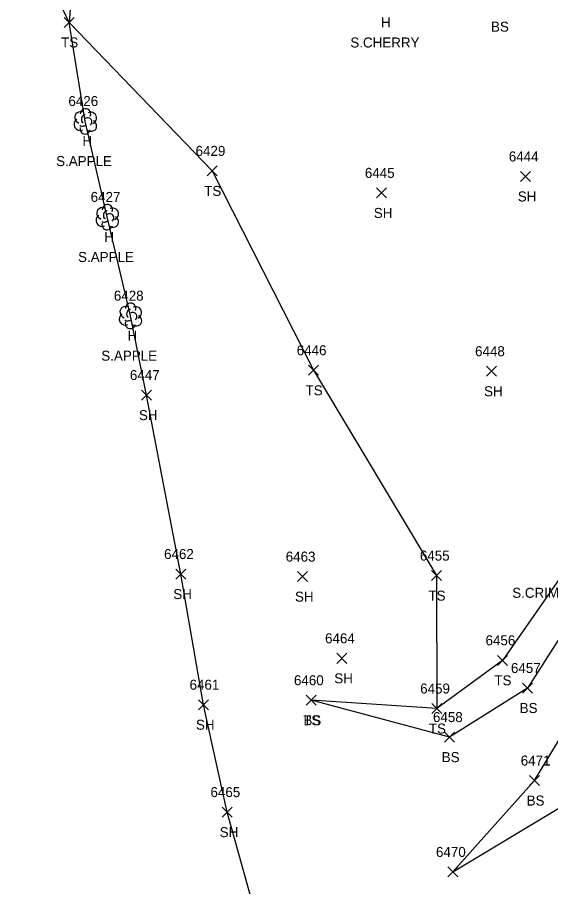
# Model space of a CAD drawing. Extents: x 1472233 to 1475777, y 540726 to 543442.
# Drawn here: x 1472240.2 to 1472346.8, y 541495 to 541668.7 of the extents above; entities that cross this region are included whole.
import ezdxf

# ---------------------------------------------------------------- set-up
doc = ezdxf.new("R2010")
doc.units = 0
for name, color, linetype in [('L_A', 7, 'Continuous'), ('L_C', 7, 'Continuous'), ('L_I', 7, 'Continuous'), ('L_TIC', 7, 'Continuous'), ('LELB', 7, 'Continuous'), ('LSOGP', 7, 'Continuous'), ('LTD', 7, 'Continuous')]:
    doc.layers.add(name, color=color, linetype=linetype)

msp = doc.modelspace()

# ---------------------------------------------------------------- linework, layer by layer
at = {"layer": 'L_TIC'}
for points in [[(1472249.53, 541666.66), (1472251.53, 541668.66)], [(1472251.53, 541666.66), (1472249.53, 541668.66)], [(1472278.15, 541636.99), (1472280.15, 541638.99)], [(1472280.15, 541636.99), (1472278.15, 541638.99)], [(1472340.77, 541635.88), (1472342.77, 541637.88)], [(1472342.77, 541635.88), (1472340.77, 541637.88)], [(1472311.99, 541632.59), (1472313.99, 541634.59)], [(1472313.99, 541632.59), (1472311.99, 541634.59)], [(1472298.42, 541597.15), (1472300.42, 541599.15)], [(1472300.42, 541597.15), (1472298.42, 541599.15)], [(1472334.03, 541596.96), (1472336.03, 541598.96)], [(1472336.03, 541596.96), (1472334.03, 541598.96)], [(1472265.01, 541592.19), (1472267.01, 541594.19)], [(1472267.01, 541592.19), (1472265.01, 541594.19)], [(1472271.89, 541556.43), (1472273.89, 541558.43)], [(1472273.89, 541556.43), (1472271.89, 541558.43)], [(1472296.21, 541555.92), (1472298.21, 541557.92)], [(1472298.21, 541555.92), (1472296.21, 541557.92)], [(1472322.99, 541556.12), (1472324.99, 541558.12)], [(1472324.99, 541556.12), (1472322.99, 541558.12)], [(1472304.08, 541539.59), (1472306.08, 541541.59)], [(1472306.08, 541539.59), (1472304.08, 541541.59)], [(1472336.17, 541539.19), (1472338.17, 541541.19)], [(1472338.17, 541539.19), (1472336.17, 541541.19)], [(1472341.19, 541533.66), (1472343.19, 541535.66)], [(1472343.19, 541533.66), (1472341.19, 541535.66)], [(1472276.42, 541530.32), (1472278.42, 541532.32)], [(1472278.42, 541530.32), (1472276.42, 541532.32)], [(1472297.94, 541531.21), (1472299.94, 541533.21)], [(1472299.94, 541531.21), (1472297.94, 541533.21)], [(1472297.94, 541531.21), (1472299.94, 541533.21)], [(1472299.94, 541531.21), (1472297.94, 541533.21)], [(1472323.06, 541529.56), (1472325.06, 541531.56)], [(1472325.06, 541529.56), (1472323.06, 541531.56)], [(1472323.06, 541529.56), (1472325.06, 541531.56)], [(1472325.06, 541529.56), (1472323.06, 541531.56)], [(1472325.61, 541523.85), (1472327.61, 541525.85)], [(1472327.61, 541523.85), (1472325.61, 541525.85)], [(1472342.59, 541515.17), (1472344.59, 541517.17)], [(1472344.59, 541515.17), (1472342.59, 541517.17)], [(1472281.16, 541508.86), (1472283.16, 541510.86)], [(1472283.16, 541508.86), (1472281.16, 541510.86)], [(1472326.29, 541496.9), (1472328.29, 541498.9)], [(1472328.29, 541496.9), (1472326.29, 541498.9)], [(1472326.29, 541496.9), (1472328.29, 541498.9)], [(1472328.29, 541496.9), (1472326.29, 541498.9)]]:
    msp.add_lwpolyline(points, dxfattribs=at)
at = {"layer": 'LELB'}
for points in [[(1472309.17, 541764.66), (1472314.54, 541746.81), (1472319.35, 541731.08), (1472317.7, 541714.57), (1472324.89, 541681.45), (1472336.46, 541670.81), (1472359.1, 541676.99), (1472364.9, 541640.23), (1472367.87, 541606.27), (1472368.21, 541581.12), (1472358.44, 541560.08), (1472342.19, 541534.66), (1472326.61, 541524.85), (1472298.94, 541532.21)], [(1472299.33, 541724.33), (1472289.98, 541730.07), (1472268.13, 541729.15), (1472253.22, 541721.94), (1472256.99, 541708.73), (1472252.51, 541693.36), (1472250.53, 541667.66), (1472279.15, 541637.99), (1472299.42, 541598.15), (1472323.99, 541557.12), (1472324.06, 541530.56)], [(1472367.87, 541606.27), (1472352.19, 541561.68), (1472337.17, 541540.19), (1472324.06, 541530.56), (1472298.94, 541532.21)], [(1472327.29, 541497.9), (1472343.59, 541516.17), (1472358.91, 541541.46), (1472365.97, 541555.39), (1472373.3, 541567.63), (1472375.91, 541562.06), (1472383.59, 541551.03), (1472407.94, 541534.18), (1472426.61, 541529.13), (1472462.11, 541538.21), (1472496.31, 541549.57), (1472514.24, 541561.59), (1472528.33, 541570.22)], [(1472327.29, 541497.9), (1472350.15, 541511.62), (1472363.37, 541538.44), (1472369.55, 541552.47), (1472375.91, 541562.06)]]:
    msp.add_lwpolyline(points, dxfattribs=at)
at = {"layer": 'LSOGP'}
msp.add_lwpolyline([(1472289.68, 541482.89), (1472282.16, 541509.86), (1472277.42, 541531.32), (1472272.89, 541557.43), (1472266.01, 541593.19), (1472262.79, 541609.06), (1472258.15, 541628.79), (1472253.76, 541647.95), (1472250.53, 541667.66), (1472240.2, 541689.37)], dxfattribs=at)
at = {"layer": 'LTD'}
for p, q in [((1472253.76, 541647.95), (1472253.76, 541647.95)), ((1472253.76, 541647.95), (1472253.76, 541647.95)), ((1472258.15, 541628.79), (1472258.15, 541628.79)), ((1472258.15, 541628.79), (1472258.15, 541628.79)), ((1472262.79, 541609.06), (1472262.79, 541609.06)), ((1472262.79, 541609.06), (1472262.79, 541609.06))]:
    msp.add_line(p, q, dxfattribs=at)
for centre in [(1472253.81, 541649.38), (1472258.2, 541630.22), (1472262.84, 541610.5)]:
    msp.add_arc(centre, 1.05, 335.5272, 180.9563, dxfattribs=at)
for centre, major_axis, ratio, start_param, end_param in [((1472252.97, 541648.62), (1.21, -0.51), 0.895232, 1.570796, 4.712389), ((1472254.81, 541648.53), (-1.14, -0.48), 0.949671, 1.570796, 4.712389), ((1472252.68, 541647.24), (0.58, -1.04), 0.959034, 3.141593, 6.283185), ((1472253.56, 541648.41), (-0.208, -0.792), 0.645439, 3.141593, 6.283185), ((1472254.26, 541647.78), (-0.5, 0.667), 0.989748, 3.141593, 6.283185), ((1472254.77, 541647.12), (-1.09, 0.79), 0.841452, 1.570796, 4.712389), ((1472253.77, 541646.45), (0.26, 1.06), 0.942809, 1.570796, 4.712389), ((1472253.31, 541647.2), (-0.625, -0.083), 0.423636, 0, 3.141593), ((1472257.36, 541629.45), (1.21, -0.51), 0.895232, 1.570796, 4.712389), ((1472259.19, 541629.37), (-1.14, -0.48), 0.949671, 1.570796, 4.712389), ((1472257.07, 541628.08), (0.58, -1.04), 0.959034, 3.141593, 6.283185), ((1472257.94, 541629.24), (-0.208, -0.792), 0.645439, 3.141593, 6.283185), ((1472258.65, 541628.62), (-0.5, 0.667), 0.989748, 3.141593, 6.283185), ((1472259.15, 541627.95), (-1.09, 0.79), 0.841452, 1.570796, 4.712389), ((1472258.15, 541627.29), (0.26, 1.06), 0.942809, 1.570796, 4.712389), ((1472257.69, 541628.04), (-0.625, -0.083), 0.423636, 0, 3.141593), ((1472262, 541609.73), (1.21, -0.51), 0.895232, 1.570796, 4.712389), ((1472262.58, 541609.52), (-0.208, -0.792), 0.645439, 3.141593, 6.283185), ((1472263.29, 541608.9), (-0.5, 0.667), 0.989748, 3.141593, 6.283185), ((1472263.83, 541609.65), (-1.14, -0.48), 0.949671, 1.570796, 4.712389), ((1472261.71, 541608.36), (0.58, -1.04), 0.959034, 3.141593, 6.283185), ((1472262.33, 541608.31), (-0.625, -0.083), 0.423636, 0, 3.141593), ((1472263.79, 541608.23), (-1.09, 0.79), 0.841452, 1.570796, 4.712389), ((1472262.79, 541607.56), (0.26, 1.06), 0.942809, 1.570796, 4.712389)]:
    msp.add_ellipse(centre, major_axis=major_axis, ratio=ratio, start_param=start_param, end_param=end_param, dxfattribs=at)

# ---------------------------------------------------------------- texts
at = {"layer": 'L_A'}
for s, p in [('H', (1472312.91, 541666.65)), ('BS', (1472334.9, 541665.81)), ('TS', (1472248.94, 541662.66)), ('H', (1472253.2, 541642.95)), ('TS', (1472277.56, 541632.99)), ('SH', (1472340.26, 541631.88)), ('SH', (1472311.47, 541628.59)), ('H', (1472257.59, 541623.79)), ('H', (1472262.23, 541604.06)), ('TS', (1472297.83, 541593.15)), ('SH', (1472333.52, 541592.96)), ('SH', (1472264.5, 541588.19)), ('SH', (1472271.37, 541552.43)), ('TS', (1472322.4, 541552.12)), ('SH', (1472295.7, 541551.92)), ('SH', (1472303.56, 541535.59)), ('TS', (1472335.58, 541535.19)), ('BS', (1472340.63, 541529.66)), ('SH', (1472275.9, 541526.32)), ('TS', (1472297.35, 541527.21)), ('BS', (1472297.39, 541527.21)), ('TS', (1472322.47, 541525.56)), ('TS', (1472322.47, 541525.56)), ('BS', (1472325.05, 541519.85)), ('BS', (1472342.03, 541511.17)), ('SH', (1472280.65, 541504.86))]:
    msp.add_text(s, height=2, dxfattribs=at).set_placement(p)
at = {"layer": 'L_C'}
for s, p in [('S.CHERRY', (1472306.78, 541662.65)), ('S.APPLE', (1472247.95, 541638.95)), ('S.APPLE', (1472252.34, 541619.79)), ('S.APPLE', (1472256.98, 541600.06)), ('S.CRIMSON MAPLE', (1472339.15, 541552.68))]:
    msp.add_text(s, height=2, dxfattribs=at).set_placement(p)
at = {"layer": 'L_I'}
for s, p in [('6426', (1472250.4, 541650.95)), ('6429', (1472275.83, 541640.99)), ('6444', (1472338.47, 541639.88)), ('6445', (1472309.68, 541636.59)), ('6427', (1472254.85, 541631.79)), ('6428', (1472259.49, 541612.06)), ('6446', (1472296.06, 541601.15)), ('6448', (1472331.72, 541600.96)), ('6447', (1472262.7, 541596.19)), ('6462', (1472269.53, 541560.43)), ('6463', (1472293.86, 541559.92)), ('6455', (1472320.68, 541560.12)), ('6464', (1472301.72, 541543.59)), ('6456', (1472333.81, 541543.19)), ('6457', (1472338.89, 541537.66)), ('6460', (1472295.5, 541535.21)), ('6460', (1472295.5, 541535.21)), ('6461', (1472274.63, 541534.32)), ('6459', (1472320.74, 541533.56)), ('6459', (1472320.74, 541533.56)), ('6458', (1472323.3, 541527.85)), ('6471', (1472340.85, 541519.17)), ('6465', (1472278.81, 541512.86)), ('6470', (1472323.9, 541500.9)), ('6470', (1472323.9, 541500.9))]:
    msp.add_text(s, height=2, dxfattribs=at).set_placement(p)

doc.saveas('drawing.dxf')
